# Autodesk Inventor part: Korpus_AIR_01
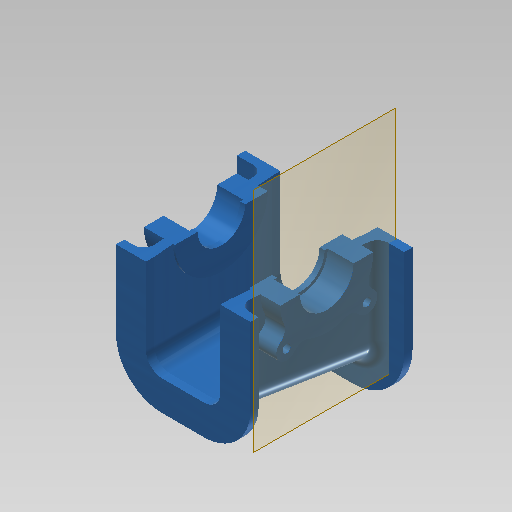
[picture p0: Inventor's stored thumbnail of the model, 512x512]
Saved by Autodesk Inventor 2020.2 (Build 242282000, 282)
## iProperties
Created: 2014-10
Part Number: Korpus_AIR_01
Material: Ogólny
Document SubType Name: Modeling
Designer: F.Stasiak
Density: 1 g/cm^3
Appearance: Cyjan
Catalog Web Link: www.expertbooks.pl
Manager: www.cadconsulting.pl
Company: Fabian Stasiak CAD Consulting
Author: F.Stasiak
Subject: Zbiór ćwiczeń. Autodesk Inventor 2020. Kurs Professional
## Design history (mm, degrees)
sketch "Szkic1"
  geometry: L1 (-56, 110)-(56, 110); L2 (56, 110)-(56, -110); L3 (56, -110)-(-56, -110); L4 (-56, -110)-(-56, 110); L5 (-56, 110)-(56, -110); L6 (56, 110)-(-56, -110); 1 further point
  constraints: 12 end point, 2 midpoint, 2 parallel, 1 horizontal, 1 perpendicular
  dimensions: "d6" = 112 distance of L2.end L3.end; "d7" = 220 distance of L1.end L2.end
extrude "Wyciągnięcie proste1" new body sketch "Szkic1" distance "d1" = 125; taper "d2" = -5 deg
fillet "Zaokrąglenie1" dims "d18" = 25
feature "Skorupa1" dims "d17" = 9
node "Płaszczyzna konstrukcyjna4"
sketch "Szkic6"
  geometry: C1 r 45 at (0, 60); 1 further point
  constraints: 1 centre point, 1 vertical alignment
  dimensions: "d20" = 90 diameter of C1; "d21" = 60 distance of point (0, 0) C1.centre
extrude "Wyciągnięcie proste4" join sketch "Szkic6" distance "d22" = 30; taper "d23" = 0 deg
sketch "Szkic7"
  geometry: L1 (0, 0)-(-38.891, -38.891); L2 (-45.962, -31.82)-(-38.095, -23.953); L3 (-33.269, -47.161)-(-24.106, -37.998); L4 (85, 0)-(-90, 0) reference; A1 r 45 centre (0, 0) between (-38.095, -23.953) and (-24.106, -37.998) reference; A2 r 10 centre (-38.891, -38.891) between (-45.29, -31.206) and (-30.621, -44.513); A3 r 55 centre (0, 0) between (-38.891, -38.891) and (-45.29, -31.206); 1 further point
  constraints: 8 point on circle, 6 end point, 2 centre point, 2 coincident, 2 parallel, 1 point on line, 1 tangent
  dimensions: "d24" = 20 diameter of A2; "d25" = 45 deg angle of L4 L1; "d26" = 110 diameter of A3
extrude "Wyciągnięcie proste5" join sketch "Szkic7" stored distance "d27" = 30; taper "d28" = 0 deg
fillet "Zaokrąglenie2" dims "d29" = 10
hole "Otwór1" diameter "d38" = 8; stored, may be unused: countersink angle "d42" = 90 deg, drill point angle "d44" = 118 deg; dims "d36" = 10, "d37" = 10, "d39" = 6, "d40" = 4, "d41" = 2, "d43" = 12
pattern_circular "Szyk kołowy1" dims angle "d31" = 360 deg
sketch "Szkic8"
  geometry: C1 r 26 at (-60, 0); A1 r 45 centre (-60, 0) between (-101.15, 18.213) and (-101.212, -18.071) reference; 1 further point
  constraints: 1 centre point, 1 coincident
  dimensions: "d33" = 52 diameter of C1
extrude "Wyciągnięcie proste6" cut sketch "Szkic8" stored distance "d34" = 30; taper "d35" = 0 deg
sketch "Szkic9"
  geometry: C1 r 26 at (0, 0) reference; C2 r 23 at (0, 0); 1 further point
  constraints: 1 centre point
  dimensions: "d45" = 3 radial gap between concentric circles of C1 C2
extrude "Wyciągnięcie proste7" join sketch "Szkic9" distance "d46" = 5; taper "d47" = 0 deg
mirror "Odbicie lustrzane2"
sketch "Szkic10"
  geometry: L1 (36.03, 74.09)-(36.03, -74.09) reference; L2 (20.09, -90.03)-(-20.09, -90.03) reference; L3 (-36.03, -74.09)-(-36.03, 74.09) reference; L4 (-20.09, 90.03)-(20.09, 90.03) reference; L5 (-45.064, -74.159)-(-45.064, 74.159) reference; L6 (20.159, -99.064)-(-20.159, -99.064) reference; L7 (45.064, 74.159)-(45.064, -74.159) reference; L8 (-20.159, 99.064)-(20.159, 99.064) reference; L9 (-20.159, 119.064)-(20.159, 119.064); L10 (65.064, 74.159)-(65.064, -74.159); L11 (20.159, -119.064)-(-20.159, -119.064); L12 (-65.064, -74.159)-(-65.064, 74.159); 9 further points; 8 other entities
  constraints: 8 end point, 7 parallel, 20 other
  dimensions: "d48" = 20 distance between parallel lines of L5 L12
extrude "Wyciągnięcie proste8" join sketch "Szkic10" distance "d49" = 8; taper "d50" = 0 deg
fillet "Zaokrąglenie3" dims "d51" = 10
sketch "Szkic11" dims "d52" = 25
  geometry: L1 (-31.027, 100.966)-(31.027, 100.966) reference; L2 (46.966, 85.027)-(46.966, -85.027) reference; L3 (31.027, -100.966)-(-31.027, -100.966) reference; L4 (-46.966, -85.027)-(-46.966, 85.027) reference; L5 (31.095, 110)-(-31.095, 110) reference; L6 (-56, 85.095)-(-56, -85.095) reference; L7 (-31.095, -110)-(31.095, -110) reference; L8 (56, -85.095)-(56, 85.095) reference; L9 (81, 85.095)-(81, -85.095); L10 (31.095, -135)-(-31.095, -135); L11 (-81, -85.095)-(-81, 85.095); L12 (-31.095, 135)-(31.095, 135); 9 further points; 8 other entities
  constraints: 8 end point, 7 parallel, 20 other
extrude "Wyciągnięcie proste9" join sketch "Szkic11" distance "d53" = 8; taper "d54" = 0 deg
fillet "Zaokrąglenie4" dims "d55" = 10
feature "Podział1"
node "Bryła1"
node "Pętla rzutowana2"
node "Pętla rzutowana3"
other parameters: "d19" = 66 (computed from d6)
